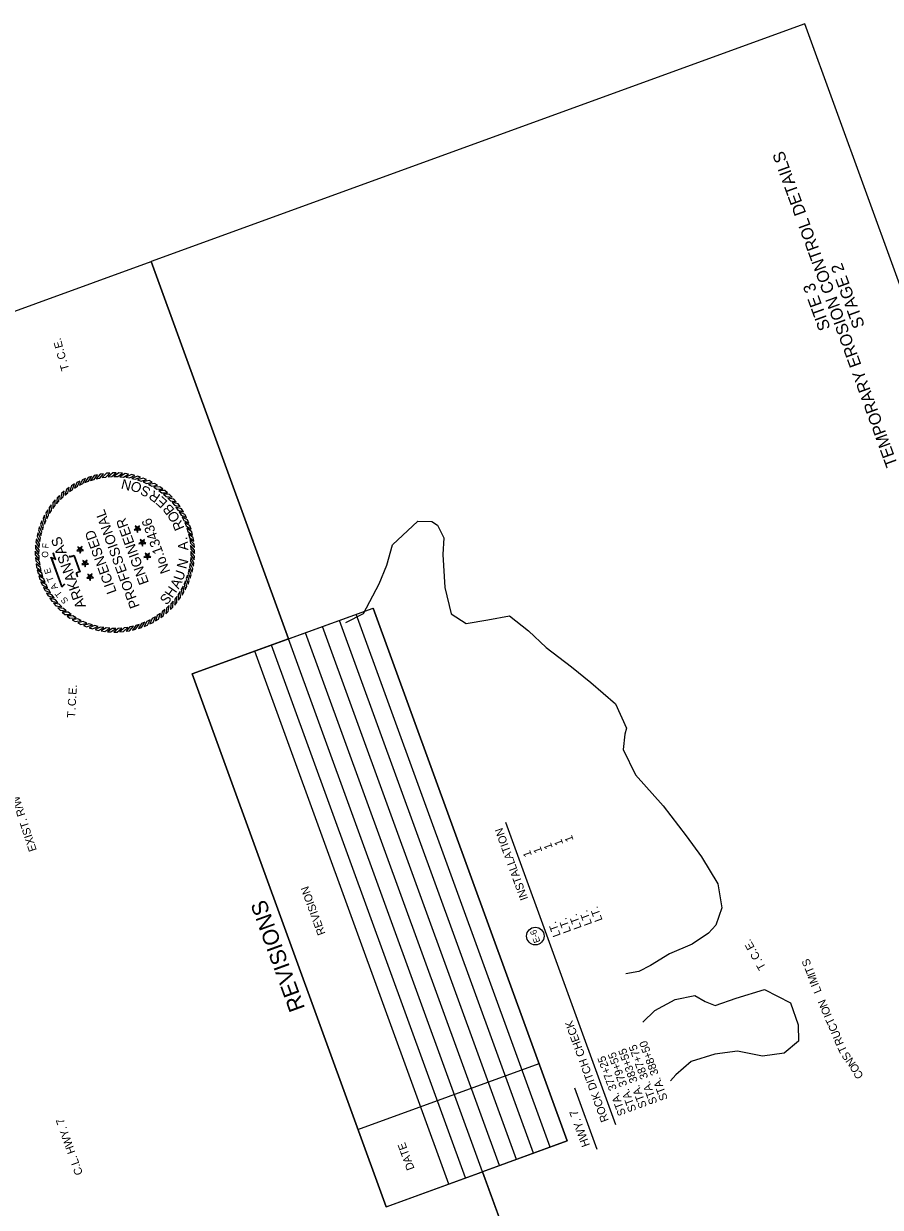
# Model space of a CAD drawing. Extents: x 960650 to 962115, y 1906452 to 1908757.
# Drawn here: x 960984 to 961626, y 1907870 to 1908757 of the extents above; entities that cross this region are included whole.
import ezdxf

# ---------------------------------------------------------------- set-up
doc = ezdxf.new("R2010")
doc.units = 0
for name, color, linetype in [('1', 7, 'Continuous'), ('44', 7, 'Continuous'), ('60', 7, 'Continuous'), ('Default', 7, 'Continuous'), ('G-ANNO-SYMB', 7, 'Continuous'), ('NO PLOT', 7, 'Continuous'), ('R_Draft', 7, 'Continuous'), ('S_TREE', 7, 'Continuous')]:
    doc.layers.add(name, color=color, linetype=linetype)

msp = doc.modelspace()

# ---------------------------------------------------------------- linework, layer by layer
at = {"layer": '1'}
for p, q in [((961182.12, 1908295.76), (961079.18, 1908578.6)), ((961425.36, 1907627.47), (961327.48, 1907896.39))]:
    msp.add_line(p, q, dxfattribs=at)
msp.add_circle((961367.02, 1908073.03), 6.61, dxfattribs=at)
at = {"layer": '44'}
for p, q in [((961427.32, 1907931.62), (961344.89, 1908158.09)), ((961413.24, 1907913), (961396.54, 1907958.89))]:
    msp.add_line(p, q, dxfattribs=at)
at = {"layer": 'Default'}
for p, q in [((961109.77, 1908269.43), (961245.55, 1908318.85)), ((961378.23, 1907914.86), (961232.87, 1908314.23)), ((961390.91, 1907919.48), (961245.55, 1908318.85)), ((961352.85, 1907905.63), (961207.49, 1908305)), ((961365.54, 1907910.24), (961220.18, 1908309.61)), ((961340.17, 1907901.01), (961194.81, 1908300.38)), ((961340.17, 1907901.01), (961194.81, 1908300.38)), ((961314.8, 1907891.78), (961169.44, 1908291.14)), ((961327.48, 1907896.39), (961182.12, 1908295.76)), ((961302.11, 1907887.16), (961156.75, 1908286.53)), ((961255.13, 1907870.06), (961109.77, 1908269.43)), ((961233.99, 1907928.14), (961369.77, 1907977.56)), ((961255.13, 1907870.06), (961390.91, 1907919.48))]:
    msp.add_line(p, q, dxfattribs=at)
at = {"layer": 'G-ANNO-SYMB'}
for points in [[(961021.59, 1908411.85), (961019.41, 1908410.49), (961017.96, 1908406.16), (961020.22, 1908407.76)], [(961025.71, 1908414.07), (961023.43, 1908412.9), (961021.64, 1908408.69), (961024.02, 1908410.11)], [(961029.99, 1908415.97), (961027.63, 1908414.97), (961025.52, 1908410.92), (961028, 1908412.15)], [(961034.41, 1908417.53), (961031.98, 1908416.72), (961029.55, 1908412.84), (961032.13, 1908413.87)], [(961038.94, 1908418.73), (961036.45, 1908418.12), (961033.73, 1908414.44), (961036.37, 1908415.26)], [(961043.54, 1908419.57), (961041.01, 1908419.16), (961038.01, 1908415.71), (961040.72, 1908416.32)], [(961048.2, 1908420.06), (961045.65, 1908419.84), (961042.39, 1908416.63), (961045.13, 1908417.03)], [(961052.89, 1908420.17), (961050.32, 1908420.15), (961046.82, 1908417.21), (961049.58, 1908417.4)], [(961057.57, 1908419.91), (961055.01, 1908420.1), (961051.28, 1908417.44), (961054.06, 1908417.41)], [(961062.21, 1908419.29), (961059.67, 1908419.68), (961055.75, 1908417.32), (961058.51, 1908417.07)], [(961066.79, 1908418.31), (961064.29, 1908418.89), (961060.2, 1908416.85), (961062.93, 1908416.39)], [(961071.28, 1908416.97), (961068.83, 1908417.75), (961064.59, 1908416.04), (961067.28, 1908415.36)], [(961075.65, 1908415.28), (961073.27, 1908416.25), (961068.91, 1908414.88), (961071.54, 1908413.99)], [(961079.87, 1908413.26), (961077.58, 1908414.41), (961073.12, 1908413.38), (961075.67, 1908412.29)], [(961083.92, 1908410.91), (961081.73, 1908412.24), (961077.21, 1908411.56), (961079.66, 1908410.27)], [(961010.44, 1908403.33), (961008.64, 1908401.51), (961008.24, 1908396.95), (961010.07, 1908399.04)], [(961013.93, 1908406.46), (961011.99, 1908404.78), (961011.24, 1908400.27), (961013.22, 1908402.21)], [(961017.65, 1908409.3), (961015.59, 1908407.78), (961014.48, 1908403.35), (961016.61, 1908405.12)], [(961087.78, 1908408.25), (961085.69, 1908409.74), (961081.13, 1908409.42), (961083.48, 1908407.95)], [(961091.41, 1908405.29), (961089.45, 1908406.95), (961084.88, 1908406.99), (961087.1, 1908405.33)], [(961094.81, 1908402.06), (961092.98, 1908403.86), (961088.42, 1908404.26), (961090.51, 1908402.44)], [(961004.26, 1908396.31), (961002.76, 1908394.22), (961003.08, 1908389.66), (961004.56, 1908392)], [(961007.21, 1908399.94), (961005.56, 1908397.98), (961005.52, 1908393.41), (961007.18, 1908395.63)], [(961097.93, 1908398.57), (961096.25, 1908400.51), (961091.74, 1908401.27), (961093.68, 1908399.29)], [(961100.78, 1908394.85), (961099.26, 1908396.92), (961094.82, 1908398.02), (961096.59, 1908395.9)], [(961103.32, 1908390.92), (961101.97, 1908393.1), (961097.63, 1908394.55), (961099.23, 1908392.29)], [(960999.25, 1908388.4), (960998.1, 1908386.1), (960999.13, 1908381.65), (961000.22, 1908384.2)], [(961001.6, 1908392.45), (961000.27, 1908390.25), (961000.95, 1908385.73), (961002.23, 1908388.19)], [(961105.55, 1908386.8), (961104.37, 1908389.08), (961100.16, 1908390.86), (961101.58, 1908388.48)], [(961107.45, 1908382.51), (961106.45, 1908384.88), (961102.39, 1908386.99), (961103.62, 1908384.51)], [(960995.53, 1908379.8), (960994.76, 1908377.36), (960996.47, 1908373.12), (960997.15, 1908375.81)], [(960997.22, 1908384.17), (960996.26, 1908381.8), (960997.63, 1908377.44), (960998.52, 1908380.06)], [(961068.86, 1908378.27), (961067.86, 1908378.55), (961066.3, 1908377.33), (961068.28, 1908377.4)], [(961068.86, 1908378.27), (961068.83, 1908379.31), (961067.18, 1908380.42), (961067.86, 1908378.55)], [(961068.86, 1908378.27), (961068.28, 1908377.4), (961068.96, 1908375.54), (961069.5, 1908377.45)], [(961068.86, 1908378.27), (961069.84, 1908378.62), (961070.39, 1908380.53), (961068.83, 1908379.31)], [(961068.86, 1908378.27), (961069.5, 1908377.45), (961071.48, 1908377.51), (961069.84, 1908378.62)], [(961109, 1908378.1), (961108.19, 1908380.53), (961104.31, 1908382.95), (961105.34, 1908380.38)], [(961110.2, 1908373.57), (961109.59, 1908376.06), (961105.91, 1908378.78), (961106.74, 1908376.13)], [(960993.21, 1908370.73), (960992.83, 1908368.2), (960995.18, 1908364.28), (960995.43, 1908367.04)], [(960994.2, 1908375.31), (960993.61, 1908372.82), (960995.65, 1908368.72), (960996.12, 1908371.46)], [(961072.59, 1908368.02), (961071.59, 1908368.3), (961070.03, 1908367.08), (961072.01, 1908367.15)], [(961072.59, 1908368.02), (961072.56, 1908369.06), (961070.91, 1908370.16), (961071.59, 1908368.3)], [(961072.59, 1908368.02), (961072.01, 1908367.15), (961072.69, 1908365.29), (961073.23, 1908367.19)], [(961072.59, 1908368.02), (961073.57, 1908368.37), (961074.12, 1908370.28), (961072.56, 1908369.06)], [(961072.59, 1908368.02), (961073.23, 1908367.19), (961075.21, 1908367.26), (961073.57, 1908368.37)], [(961111.05, 1908368.96), (961110.63, 1908371.49), (961107.18, 1908374.49), (961107.79, 1908371.79)], [(961111.53, 1908364.3), (961111.31, 1908366.86), (961108.11, 1908370.12), (961108.51, 1908367.38)], [(960992.34, 1908361.41), (960992.35, 1908358.85), (960995.29, 1908355.35), (960995.11, 1908358.11)], [(960992.59, 1908366.09), (960992.41, 1908363.53), (960995.06, 1908359.81), (960995.1, 1908362.58)], [(961025.93, 1908362.64), (961024.93, 1908362.93), (961023.37, 1908361.71), (961025.35, 1908361.78)], [(961025.93, 1908362.64), (961025.9, 1908363.68), (961024.26, 1908364.79), (961024.93, 1908362.93)], [(961025.93, 1908362.64), (961025.35, 1908361.78), (961026.03, 1908359.92), (961026.58, 1908361.82)], [(961025.93, 1908362.64), (961026.91, 1908363), (961027.46, 1908364.9), (961025.9, 1908363.68)], [(961025.93, 1908362.64), (961026.58, 1908361.82), (961028.56, 1908361.89), (961026.91, 1908363)], [(961076.32, 1908357.76), (961076.29, 1908358.8), (961074.65, 1908359.91), (961075.32, 1908358.05)], [(961076.32, 1908357.76), (961077.3, 1908358.12), (961077.85, 1908360.02), (961076.29, 1908358.8)], [(961076.32, 1908357.76), (961076.97, 1908356.94), (961078.95, 1908357.01), (961077.3, 1908358.12)], [(961111.64, 1908359.62), (961111.63, 1908362.18), (961108.69, 1908365.69), (961108.87, 1908362.92)], [(961111.39, 1908354.94), (961111.57, 1908357.5), (961108.92, 1908361.22), (961108.88, 1908358.45)], [(960992.45, 1908356.73), (960992.67, 1908354.17), (960995.87, 1908350.91), (960995.47, 1908353.66)], [(960992.93, 1908352.07), (960993.35, 1908349.54), (960996.8, 1908346.54), (960996.19, 1908349.24)], [(961029.67, 1908352.39), (961028.66, 1908352.68), (961027.1, 1908351.46), (961029.08, 1908351.53)], [(961029.67, 1908352.39), (961029.63, 1908353.43), (961027.99, 1908354.54), (961028.66, 1908352.68)], [(961029.67, 1908352.39), (961029.08, 1908351.53), (961029.76, 1908349.67), (961030.31, 1908351.57)], [(961029.67, 1908352.39), (961030.64, 1908352.75), (961031.19, 1908354.65), (961029.63, 1908353.43)], [(961029.67, 1908352.39), (961030.31, 1908351.57), (961032.29, 1908351.64), (961030.64, 1908352.75)], [(961076.32, 1908357.76), (961075.32, 1908358.05), (961073.76, 1908356.83), (961075.74, 1908356.9)], [(961076.32, 1908357.76), (961075.74, 1908356.9), (961076.42, 1908355.04), (961076.97, 1908356.94)], [(961109.78, 1908345.72), (961110.37, 1908348.22), (961108.33, 1908352.31), (961107.86, 1908349.58)], [(961110.77, 1908350.3), (961111.15, 1908352.83), (961108.8, 1908356.75), (961108.55, 1908353.99)], [(960993.78, 1908347.46), (960994.39, 1908344.97), (960998.07, 1908342.25), (960997.24, 1908344.9)], [(960994.98, 1908342.94), (960995.79, 1908340.5), (960999.67, 1908338.08), (960998.64, 1908340.65)], [(961033.4, 1908342.14), (961032.4, 1908342.43), (961030.83, 1908341.21), (961032.81, 1908341.28)], [(961033.4, 1908342.14), (961033.36, 1908343.18), (961031.72, 1908344.29), (961032.4, 1908342.43)], [(961033.4, 1908342.14), (961032.81, 1908341.28), (961033.49, 1908339.41), (961034.04, 1908341.32)], [(961033.4, 1908342.14), (961034.38, 1908342.5), (961034.92, 1908344.4), (961033.36, 1908343.18)], [(961033.4, 1908342.14), (961034.04, 1908341.32), (961036.02, 1908341.39), (961034.38, 1908342.5)], [(961106.76, 1908336.86), (961107.72, 1908339.24), (961106.35, 1908343.6), (961105.46, 1908340.97)], [(961108.45, 1908341.23), (961109.22, 1908343.67), (961107.51, 1908347.91), (961106.83, 1908345.23)], [(960996.53, 1908338.52), (960997.53, 1908336.15), (961001.59, 1908334.04), (961000.36, 1908336.53)], [(960998.43, 1908334.23), (960999.61, 1908331.96), (961003.82, 1908330.17), (961002.4, 1908332.55)], [(961102.38, 1908328.58), (961103.71, 1908330.78), (961103.03, 1908335.3), (961101.75, 1908332.85)], [(961104.73, 1908332.63), (961105.88, 1908334.93), (961104.85, 1908339.38), (961103.76, 1908336.84)], [(961000.66, 1908330.11), (961002.01, 1908327.93), (961006.35, 1908326.48), (961004.75, 1908328.75)], [(961003.2, 1908326.18), (961004.72, 1908324.11), (961009.16, 1908323.01), (961007.39, 1908325.14)], [(961093.54, 1908317.7), (961095.34, 1908319.53), (961095.74, 1908324.08), (961093.91, 1908322)], [(961096.77, 1908321.09), (961098.42, 1908323.05), (961098.46, 1908327.63), (961096.8, 1908325.4)], [(961099.72, 1908324.73), (961101.22, 1908326.81), (961100.9, 1908331.37), (961099.42, 1908329.03)], [(961006.05, 1908322.46), (961007.73, 1908320.52), (961012.24, 1908319.76), (961010.3, 1908321.75)], [(961009.17, 1908318.97), (961011, 1908317.17), (961015.56, 1908316.77), (961013.47, 1908318.59)], [(961012.57, 1908315.74), (961014.53, 1908314.09), (961019.1, 1908314.05), (961016.88, 1908315.7)], [(961082.39, 1908309.18), (961084.57, 1908310.54), (961086.02, 1908314.88), (961083.76, 1908313.27)], [(961086.33, 1908311.73), (961088.39, 1908313.25), (961089.5, 1908317.69), (961087.37, 1908315.91)], [(961090.05, 1908314.57), (961091.99, 1908316.25), (961092.74, 1908320.76), (961090.76, 1908318.83)], [(961016.2, 1908312.78), (961018.29, 1908311.29), (961022.85, 1908311.61), (961020.5, 1908313.08)], [(961020.06, 1908310.12), (961022.25, 1908308.8), (961026.77, 1908309.47), (961024.32, 1908310.76)], [(961024.11, 1908307.77), (961026.4, 1908306.62), (961030.86, 1908307.65), (961028.31, 1908308.74)], [(961028.33, 1908305.75), (961030.71, 1908304.78), (961035.07, 1908306.16), (961032.44, 1908307.04)], [(961032.7, 1908304.06), (961035.15, 1908303.28), (961039.39, 1908305), (961036.7, 1908305.68)], [(961060.43, 1908301.46), (961062.97, 1908301.88), (961065.97, 1908305.33), (961063.26, 1908304.71)], [(961065.04, 1908302.3), (961067.53, 1908302.92), (961070.25, 1908306.59), (961067.61, 1908305.77)], [(961069.57, 1908303.51), (961072, 1908304.31), (961074.43, 1908308.19), (961071.85, 1908307.16)], [(961073.99, 1908305.06), (961076.35, 1908306.06), (961078.46, 1908310.11), (961075.98, 1908308.89)], [(961078.27, 1908306.96), (961080.55, 1908308.14), (961082.34, 1908312.35), (961079.96, 1908310.93)], [(961037.19, 1908302.72), (961039.69, 1908302.14), (961043.78, 1908304.18), (961041.05, 1908304.65)], [(961041.77, 1908301.74), (961044.31, 1908301.35), (961048.23, 1908303.71), (961045.47, 1908303.96)], [(961046.41, 1908301.12), (961048.97, 1908300.93), (961052.7, 1908303.59), (961049.92, 1908303.62)], [(961051.09, 1908300.86), (961053.66, 1908300.88), (961057.16, 1908303.82), (961054.39, 1908303.63)], [(961055.78, 1908300.98), (961058.33, 1908301.19), (961061.59, 1908304.4), (961058.85, 1908304)]]:
    msp.add_lwpolyline(points, close=True, dxfattribs=at)
for points in [[(961014.57, 1908336.73), (961012.22, 1908334.39), (961003.97, 1908357), (961007.03, 1908355.97), (961006.45, 1908357.5), (961005.97, 1908358.78), (961005.64, 1908360.11)], [(961014.3, 1908337), (961012.37, 1908335.08), (961004.6, 1908356.38), (961007.67, 1908355.35), (961006.81, 1908357.63), (961006.34, 1908358.89), (961006.01, 1908360.2)], [(961017.59, 1908357.92), (961018.04, 1908357.65), (961018.56, 1908357.69), (961019.78, 1908357.99), (961021.34, 1908358.56), (961025.93, 1908345.93), (961023.82, 1908345.16), (961023.36, 1908344.99), (961023.39, 1908344.43), (961024.04, 1908342.63), (961023.67, 1908342.13)], [(961017.39, 1908357.59), (961017.95, 1908357.26), (961018.62, 1908357.31), (961019.89, 1908357.62), (961021.11, 1908358.07), (961025.45, 1908346.16), (961023.69, 1908345.52), (961022.96, 1908345.26), (961023.01, 1908344.35), (961023.61, 1908342.69), (961023.36, 1908342.36)]]:
    msp.add_lwpolyline(points, dxfattribs=at)
at = {"layer": 'NO PLOT'}
for points in [[(962114.55, 1907257.7), (961568.91, 1908756.85), (961079.18, 1908578.6), (961182.12, 1908295.76), (961245.55, 1908318.85), (961390.91, 1907919.48), (961327.48, 1907896.39), (961425.36, 1907627.47), (961483.4, 1907648.6), (961600.59, 1907326.6), (961542.56, 1907305.48), (961624.82, 1907079.46)], [(962114.55, 1907257.7), (961568.91, 1908756.85), (961079.18, 1908578.6), (961182.12, 1908295.76), (961245.55, 1908318.85), (961390.91, 1907919.48), (961327.48, 1907896.39), (961425.36, 1907627.47), (961483.4, 1907648.6), (961600.59, 1907326.6), (961542.56, 1907305.48), (961624.82, 1907079.46)], [(962114.55, 1907257.7), (961568.91, 1908756.85), (961079.18, 1908578.6), (961182.12, 1908295.76), (961245.55, 1908318.85), (961390.91, 1907919.48), (961327.48, 1907896.39), (961425.36, 1907627.47), (961483.4, 1907648.6), (961600.59, 1907326.6), (961542.56, 1907305.48), (961624.82, 1907079.46)], [(962114.55, 1907257.7), (961568.91, 1908756.85), (961079.18, 1908578.6), (961182.12, 1908295.76), (961245.55, 1908318.85), (961390.91, 1907919.48), (961327.48, 1907896.39), (961425.36, 1907627.47), (961483.4, 1907648.6), (961600.59, 1907326.6), (961542.56, 1907305.48), (961624.82, 1907079.46)], [(962114.55, 1907257.7), (961568.91, 1908756.85), (961079.18, 1908578.6), (961182.12, 1908295.76), (961245.55, 1908318.85), (961390.91, 1907919.48), (961327.48, 1907896.39), (961425.36, 1907627.47), (961483.4, 1907648.6), (961600.59, 1907326.6), (961542.56, 1907305.48), (961624.82, 1907079.46)], [(961135.09, 1906901.21), (960730.12, 1908013.86), (960776.54, 1908030.76), (960709.57, 1908214.75), (960723.29, 1908219.74), (960649.59, 1908422.25), (961079.18, 1908578.6), (961182.12, 1908295.76), (961109.77, 1908269.43), (961255.13, 1907870.06), (961327.48, 1907896.39), (961425.36, 1907627.47), (961369.64, 1907607.19), (961486.84, 1907285.2), (961542.56, 1907305.48), (961624.82, 1907079.46)], [(961135.09, 1906901.21), (960730.12, 1908013.86), (960776.54, 1908030.76), (960709.57, 1908214.75), (960723.29, 1908219.74), (960649.59, 1908422.25), (961079.18, 1908578.6), (961182.12, 1908295.76), (961109.77, 1908269.43), (961255.13, 1907870.06), (961327.48, 1907896.39), (961425.36, 1907627.47), (961369.64, 1907607.19), (961486.84, 1907285.2), (961542.56, 1907305.48), (961624.82, 1907079.46)], [(961135.09, 1906901.21), (960730.12, 1908013.86), (960776.54, 1908030.76), (960709.57, 1908214.75), (960723.29, 1908219.74), (960649.59, 1908422.25), (961079.18, 1908578.6), (961182.12, 1908295.76), (961109.77, 1908269.43), (961255.13, 1907870.06), (961327.48, 1907896.39), (961425.36, 1907627.47), (961369.64, 1907607.19), (961486.84, 1907285.2), (961542.56, 1907305.48), (961624.82, 1907079.46)], [(961135.09, 1906901.21), (960730.12, 1908013.86), (960776.54, 1908030.76), (960709.57, 1908214.75), (960723.29, 1908219.74), (960649.59, 1908422.25), (961079.18, 1908578.6), (961182.12, 1908295.76), (961109.77, 1908269.43), (961255.13, 1907870.06), (961327.48, 1907896.39), (961425.36, 1907627.47), (961369.64, 1907607.19), (961486.84, 1907285.2), (961542.56, 1907305.48), (961624.82, 1907079.46)], [(961135.09, 1906901.21), (960730.12, 1908013.86), (960776.54, 1908030.76), (960709.57, 1908214.75), (960723.29, 1908219.74), (960649.59, 1908422.25), (961079.18, 1908578.6), (961182.12, 1908295.76), (961109.77, 1908269.43), (961255.13, 1907870.06), (961327.48, 1907896.39), (961425.36, 1907627.47), (961369.64, 1907607.19), (961486.84, 1907285.2), (961542.56, 1907305.48), (961624.82, 1907079.46)]]:
    msp.add_lwpolyline(points, close=True, dxfattribs=at)
at = {"layer": 'S_TREE'}
for points in [[(961225.09, 1908307.95), (961238.21, 1908314.7), (961249.93, 1908337.08), (961255.86, 1908350.99), (961259.89, 1908366.16), (961279.08, 1908383.94), (961289.44, 1908383.61), (961293.79, 1908380.93), (961298.4, 1908371.55), (961297.58, 1908358.9), (961299.11, 1908334.24), (961304, 1908314.48), (961315.28, 1908307.21), (961331.48, 1908310.11), (961347.54, 1908313.05), (961361.94, 1908301.67), (961375.06, 1908289.3), (961394.1, 1908274.92), (961408.66, 1908263.18), (961427.12, 1908247.17), (961435.32, 1908228.76), (961434.11, 1908224.37), (961432.9, 1908212.83), (961442.09, 1908193.88), (961462.79, 1908170.51), (961480.13, 1908148.13), (961491.56, 1908132.3), (961503.74, 1908112.25), (961506.85, 1908094.24), (961502.35, 1908081.29), (961496.86, 1908075.17), (961484.46, 1908066.87), (961467.46, 1908059.58), (961453.33, 1908050.96), (961444.45, 1908046.37), (961434.88, 1908044.79)], [(961447.6, 1908008.38), (961456.45, 1908017.1), (961471.76, 1908025.41), (961486.61, 1908028.57), (961494.18, 1908023.95), (961501.89, 1908020.88), (961517.54, 1908026.43), (961538.68, 1908032.85), (961558.21, 1908022.96), (961564.06, 1908006.37), (961564.2, 1907994.29), (961553.37, 1907985.35), (961537.17, 1907983), (961518.41, 1907986.71), (961501.46, 1907984.44), (961483.69, 1907979), (961472.26, 1907969.05), (961468.2, 1907964.48)]]:
    msp.add_lwpolyline(points, dxfattribs=at)

# ---------------------------------------------------------------- texts
at = {"layer": '1'}
msp.add_text('E-6 ', height=4.8, rotation=110, dxfattribs=at).set_placement((961370.82, 1908068.88))
at = {"layer": '44'}
for s, height, p in [('INSTALLATION', 6, (961361.66, 1908101.03)), ('1', 6, (961387.98, 1908142.06)), ('1', 6, (961395.81, 1908144.91)), ('1', 6, (961364.49, 1908133.51)), ('1', 6, (961372.32, 1908136.36)), ('1', 6, (961380.15, 1908139.21)), ('LT.', 6, (961409.61, 1908082.15)), ('LT.', 6, (961417.44, 1908085)), ('LT.', 6, (961386.12, 1908073.6)), ('LT.', 6, (961393.95, 1908076.45)), ('LT.', 6, (961401.78, 1908079.3)), ('ROCK DITCH CHECK', 6, (961422.15, 1907934.84)), ('STA. 379+55', 6, (961442.9, 1907942.39)), ('STA. 383+55', 6, (961450.73, 1907945.24)), ('STA. 387+75', 6, (961458.56, 1907948.09)), ('STA. 388+50', 6, (961466.39, 1907950.94)), ('STA. 377+25', 6, (961435.07, 1907939.54)), ('HWY. 7', 6.25, (961408.03, 1907916.26))]:
    msp.add_text(s, height=height, rotation=110, dxfattribs=at).set_placement(p)
at = {"layer": '60'}
for s, p in [('TEMPORARY EROSION CONTROL DETAILS', (961638.71, 1908426.37)), ('STAGE 2', (961614.01, 1908530.43)), ('SITE 3', (961588.3, 1908528.69))]:
    msp.add_text(s, height=9, rotation=110, dxfattribs=at).set_placement(p)
at = {"layer": 'Default'}
for s, height, p in [('REVISION', 6, (961209.83, 1908074.9)), ('REVISIONS', 12, (961194.57, 1908018.9)), ('DATE', 6, (961276.6, 1907898.78))]:
    msp.add_text(s, height=height, rotation=110, dxfattribs=at).set_placement(p)
at = {"layer": 'G-ANNO-SYMB'}
for s, height, rotation, p in [('N', 7.5, 166.10067, (961064.95, 1908413.91)), ('O', 7.5, 154.77573, (961073.07, 1908411.32)), ('S', 7.5, 153.48784, (961079.51, 1908408.18)), ('R', 7.5, 145.65967, (961086.66, 1908403.44)), ('E', 7.5, 137.83149, (961091.95, 1908398.62)), ('B', 7.5, 128.88501, (961097.08, 1908392.43)), ('PROFESSIONAL', 7.5, 110, (961070.66, 1908320.18)), ('ENGINEER', 7.5, 110, (961077.56, 1908337.9)), ('No.13436', 7.47, 110, (961093.55, 1908346.24)), ('O', 7.5, 121.42961, (961101.15, 1908385.91)), ('R', 7.5, 113.22866, (961104.23, 1908378.87)), ('LICENSED', 7.5, 110, (961053.38, 1908331)), ('F', 4.75, 85.36282, (961002.2, 1908363.5)), ('ARKANSAS', 7.747, 110, (961030.44, 1908320.09)), ('A', 7.5, 93.09908, (961106.95, 1908362.23)), ('.', 7.5, 101.30002, (961106.48, 1908369.9)), ('O', 4.75, 91.2218, (961002.04, 1908356.64)), ('N', 7.5, 74.93262, (961105.38, 1908347.74)), ('E', 4.75, 106.67203, (961004.45, 1908345.25)), ('T', 4.75, 111.47887, (961006.39, 1908339.49)), ('U', 7.5, 70.90262, (961102.71, 1908338.73)), ('A', 4.75, 118.67877, (961009.38, 1908334.05)), ('H', 7.5, 55.61905, (961094.91, 1908325.84)), ('A', 7.5, 63.44722, (961099.72, 1908332.66)), ('T', 4.75, 126.90148, (961012.76, 1908329.15)), ('S', 4.75, 129.77256, (961017.37, 1908324.41)), ('S', 7.5, 48.16364, (961090.56, 1908320.62))]:
    msp.add_text(s, height=height, rotation=rotation, dxfattribs=at).set_placement(p)
at = {"layer": 'R_Draft'}
for s, rotation, p in [('E', 105.28135, (961013.19, 1908514.39)), ('.', 105.28135, (961011.77, 1908519.59)), ('C', 105.28135, (961015.45, 1908506.1)), ('.', 105.28135, (961013.96, 1908511.57)), ('T', 105.28135, (961017.77, 1908497.62)), ('.', 105.28135, (961016.23, 1908503.27)), ('.', 86.55243, (961023.43, 1908259.15)), ('E', 86.55243, (961023.1, 1908253.77)), ('.', 86.55243, (961022.93, 1908250.85)), ('C', 86.55243, (961022.59, 1908245.19)), ('.', 86.55243, (961022.41, 1908242.27)), ('T', 86.55243, (961022.06, 1908236.42)), ('EXIST. R/W', 108.04695, (960993.49, 1908137.45)), ('E', 119.15275, (961531.55, 1908064.65)), ('.', 119.15275, (961528.92, 1908069.36)), ('C', 119.15275, (961535.74, 1908057.14)), ('.', 119.15275, (961532.97, 1908062.09)), ('T', 119.15275, (961540.02, 1908049.47)), ('.', 119.15275, (961537.16, 1908054.58)), ('S', 113.74045, (961573.96, 1908051.73)), ('T', 111.84067, (961576.17, 1908046.31)), ('I', 111.84067, (961576.91, 1908044.47)), ('M', 107.66338, (961578.7, 1908038.29)), ('I', 112.80637, (961579.62, 1908036.51)), ('L', 112.58628, (961581.68, 1908031.54)), ('N', 113.32394, (961586.22, 1908020.79)), ('O', 112.89729, (961588.51, 1908015.4)), ('I', 112.89729, (961589.28, 1908013.57)), ('T', 115.67801, (961591.76, 1908008.26)), ('C', 113.40163, (961593.99, 1908003.05)), ('U', 112.14652, (961596.16, 1907997.71)), ('R', 113.47507, (961598.35, 1907992.48)), ('T', 115.1863, (961600.85, 1907987.18)), ('S', 126.56259, (961604.13, 1907982.56)), ('N', 125.28153, (961607.4, 1907977.92)), ('O', 121.68925, (961610.46, 1907972.93)), ('C', 118.13251, (961613.11, 1907967.92)), ('C.L. HWY. 7', 109.51989, (961028.11, 1907895))]:
    msp.add_text(s, height=6, rotation=rotation, dxfattribs=at).set_placement(p)

doc.saveas('drawing.dxf')
